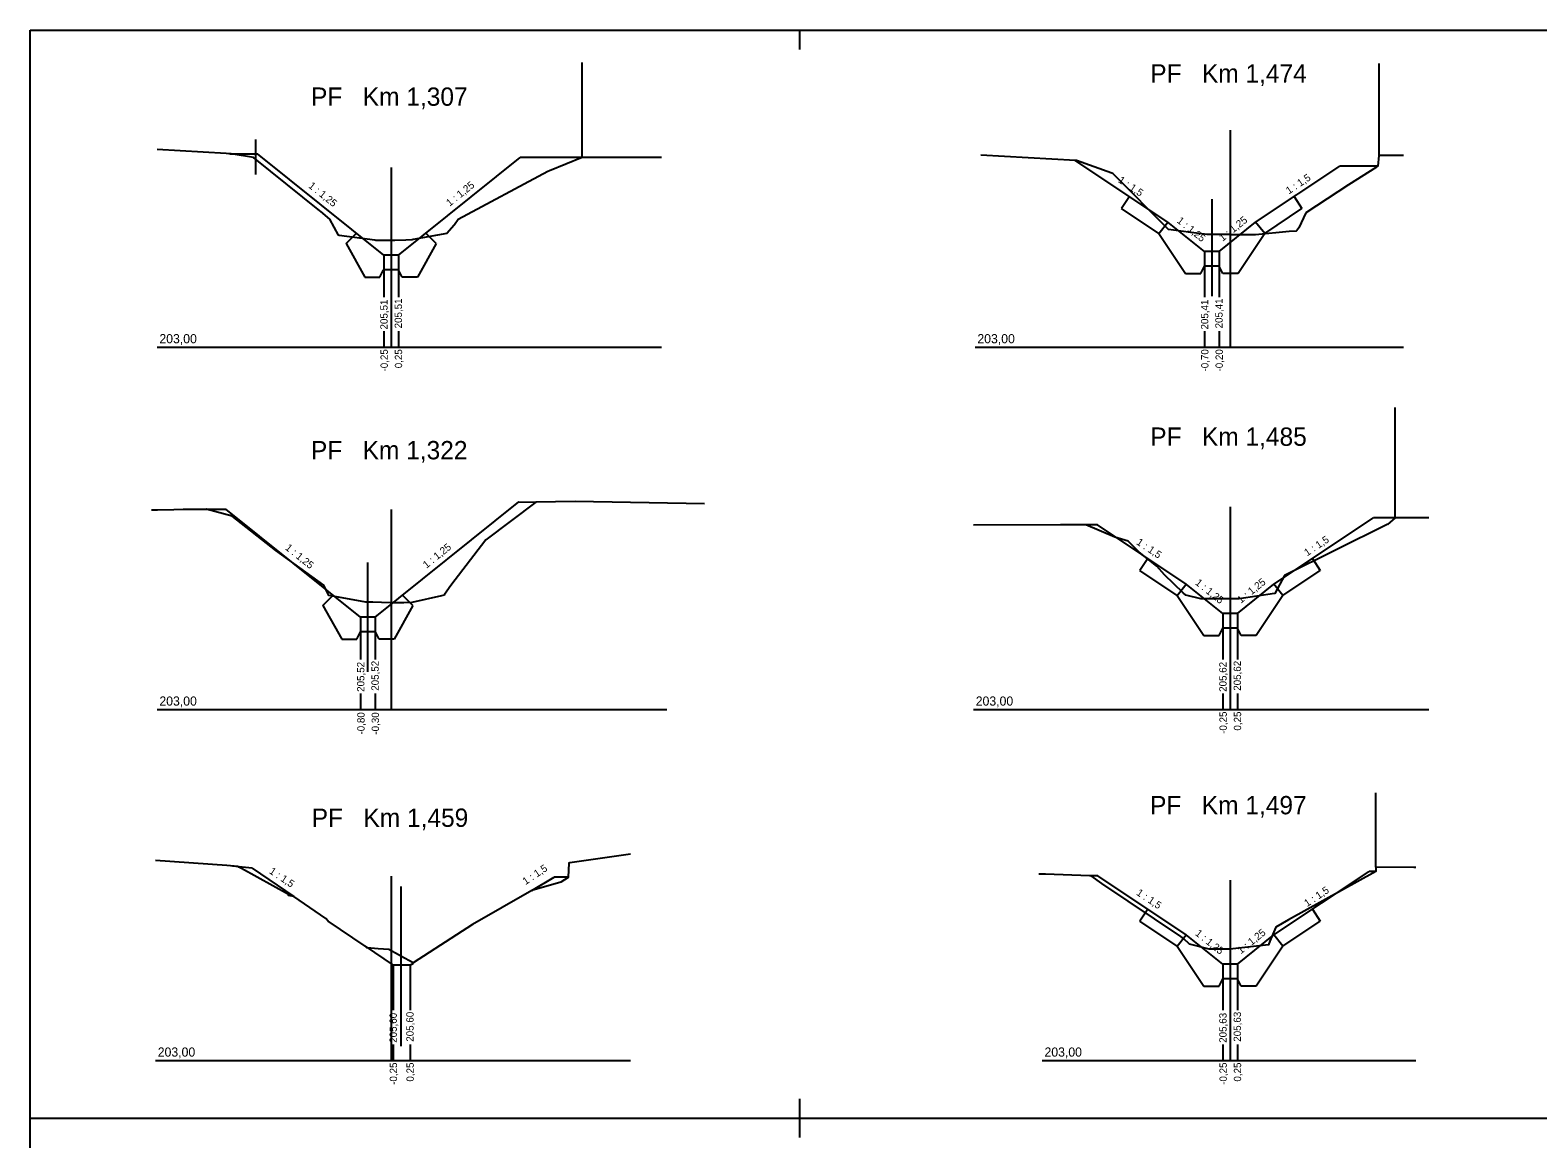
# Model space of a CAD drawing. Extents: x -547174 to -543113, y -1125006 to -1123643.
# Drawn here: x -547152.27 to -547111.11, y -1123808.23 to -1123777.97 of the extents above; entities that cross this region are included whole.
import ezdxf

# ---------------------------------------------------------------- set-up
doc = ezdxf.new("R2010")
doc.units = 0
for name, color, linetype in [('Default', 7, 'Continuous'), ('Profile', 7, 'Continuous'), ('PROFILY NÁVRH', 7, 'Continuous'), ('Section', 7, 'Continuous'), ('STANIČENÍ', 7, 'Continuous')]:
    doc.layers.add(name, color=color, linetype=linetype)

msp = doc.modelspace()

# ---------------------------------------------------------------- linework, layer by layer
at = {"layer": 'Default'}
for points in [[(-547135.036, -1123781.443), (-547137.203, -1123781.442), (-547138.098, -1123781.806), (-547138.143, -1123781.825), (-547140.584, -1123783.136), (-547140.692, -1123783.277), (-547140.699, -1123783.287), (-547140.897, -1123783.518), (-547141.812, -1123783.683), (-547141.841, -1123783.69), (-547142.018, -1123783.695), (-547142.318, -1123783.709), (-547142.34, -1123783.71), (-547142.834, -1123783.71), (-547142.862, -1123783.703), (-547143.838, -1123783.575), (-547143.851, -1123783.559), (-547144.095, -1123783.125), (-547144.334, -1123782.917), (-547144.368, -1123782.894), (-547146.171, -1123781.444), (-547146.781, -1123781.343), (-547146.847, -1123781.34), (-547146.919, -1123781.336), (-547148.807, -1123781.222)], [(-547114.777, -1123781.389), (-547115.442, -1123781.388), (-547115.455, -1123781.389), (-547115.482, -1123781.677), (-547115.484, -1123781.678), (-547115.492, -1123781.682), (-547115.519, -1123781.702), (-547116.277, -1123782.19), (-547117.45, -1123782.95), (-547117.633, -1123783.367), (-547117.689, -1123783.433), (-547117.702, -1123783.445), (-547117.706, -1123783.449), (-547117.899, -1123783.466), (-547118.824, -1123783.553), (-547118.842, -1123783.552), (-547119.489, -1123783.551), (-547119.492, -1123783.549), (-547120.143, -1123783.549), (-547120.144, -1123783.549), (-547120.654, -1123783.482), (-547121.191, -1123783.411), (-547121.194, -1123783.41), (-547121.2, -1123783.404), (-547122.698, -1123781.901), (-547122.718, -1123781.881), (-547122.743, -1123781.874), (-547123.704, -1123781.521), (-547123.737, -1123781.521), (-547126.315, -1123781.375)], [(-547133.864, -1123790.897), (-547137.392, -1123790.831), (-547138.466, -1123790.849), (-547139.83, -1123791.877), (-547140.787, -1123793.125), (-547140.96, -1123793.376), (-547140.974, -1123793.393), (-547141.039, -1123793.405), (-547141.855, -1123793.595), (-547142.069, -1123793.602), (-547142.445, -1123793.601), (-547142.921, -1123793.584), (-547143.104, -1123793.584), (-547144.054, -1123793.405), (-547144.122, -1123793.397), (-547144.122, -1123793.397), (-547144.139, -1123793.366), (-547144.255, -1123793.115), (-547145.569, -1123792.172), (-547146.755, -1123791.236), (-547147.466, -1123791.041), (-547148.797, -1123791.066), (-547148.96, -1123791.066)], [(-547114.086, -1123791.281), (-547114.949, -1123791.279), (-547115.008, -1123791.278), (-547115.22, -1123791.457), (-547115.225, -1123791.464), (-547118.009, -1123792.841), (-547118.025, -1123792.85), (-547118.026, -1123792.853), (-547118.295, -1123793.346), (-547118.301, -1123793.347), (-547119.264, -1123793.491), (-547119.959, -1123793.491), (-547119.96, -1123793.491), (-547119.961, -1123793.491), (-547120.294, -1123793.492), (-547120.31, -1123793.492), (-547120.31, -1123793.492), (-547120.721, -1123793.389), (-547120.795, -1123793.324), (-547121.304, -1123792.831), (-547121.515, -1123792.595), (-547121.997, -1123792.218), (-547122.299, -1123791.916), (-547122.663, -1123791.809), (-547123.448, -1123791.473), (-547124.141, -1123791.473), (-547126.521, -1123791.477)], [(-547135.88, -1123800.459), (-547137.542, -1123800.7), (-547137.57, -1123800.709), (-547137.581, -1123801.085), (-547137.582, -1123801.095), (-547137.782, -1123801.222), (-547138.573, -1123801.454), (-547140.197, -1123802.383), (-547141.815, -1123803.43), (-547142.149, -1123803.248), (-547142.15, -1123803.248), (-547142.151, -1123803.248), (-547142.218, -1123803.21), (-547142.476, -1123803.067), (-547142.477, -1123803.067), (-547142.774, -1123803.043), (-547143.069, -1123803.019), (-547143.081, -1123803.02), (-547143.083, -1123803.021), (-547143.129, -1123802.972), (-547144.134, -1123802.286), (-547144.203, -1123802.22), (-547145.075, -1123801.617), (-547145.216, -1123801.585), (-547145.224, -1123801.565), (-547146.507, -1123800.854), (-547146.571, -1123800.815), (-547146.6, -1123800.802), (-547146.901, -1123800.773), (-547148.852, -1123800.633)], [(-547114.444, -1123800.827), (-547114.498, -1123800.828), (-547115.534, -1123800.816), (-547115.533, -1123800.932), (-547115.537, -1123800.938), (-547117.916, -1123802.253), (-547118.262, -1123802.453), (-547118.425, -1123802.836), (-547118.462, -1123802.933), (-547119.521, -1123803.053), (-547119.523, -1123803.053), (-547119.525, -1123803.053), (-547119.909, -1123803.053), (-547119.91, -1123803.053), (-547120.079, -1123803.053), (-547120.082, -1123803.052), (-547120.618, -1123802.922), (-547120.623, -1123802.918), (-547120.787, -1123802.76), (-547120.857, -1123802.713), (-547123.014, -1123801.259), (-547123.309, -1123801.054), (-547123.353, -1123801.051), (-547124.551, -1123801.004), (-547124.738, -1123801.007)]]:
    msp.add_lwpolyline(points, dxfattribs=at)
at = {"layer": 'Profile'}
for p, q in [((-547152.272, -1123777.966), (-547131.272, -1123777.966)), ((-547152.272, -1123807.666), (-547152.272, -1123777.966)), ((-547131.272, -1123777.966), (-547110.272, -1123777.966)), ((-547131.272, -1123777.966), (-547131.272, -1123778.494)), ((-547131.272, -1123807.138), (-547131.272, -1123807.666)), ((-547152.272, -1123807.666), (-547138.818, -1123807.666)), ((-547152.272, -1123807.666), (-547131.272, -1123807.666)), ((-547152.272, -1123837.366), (-547152.272, -1123807.666)), ((-547131.272, -1123807.666), (-547115.303, -1123807.666)), ((-547131.272, -1123807.666), (-547110.272, -1123807.666)), ((-547131.272, -1123807.666), (-547131.272, -1123808.194))]:
    msp.add_line(p, q, dxfattribs=at)
at = {"layer": 'PROFILY NÁVRH'}
for p, q in [((-547146.118, -1123780.955), (-547146.118, -1123781.906)), ((-547146.814, -1123781.342), (-547146.067, -1123781.342)), ((-547142.618, -1123784.109), (-547146.067, -1123781.342)), ((-547142.218, -1123784.109), (-547138.893, -1123781.442)), ((-547137.203, -1123781.442), (-547138.893, -1123781.442)), ((-547121.21, -1123783.209), (-547123.743, -1123781.52)), ((-547118.816, -1123783.209), (-547116.518, -1123781.677)), ((-547115.48, -1123781.677), (-547116.518, -1123781.677)), ((-547122.258, -1123782.511), (-547122.476, -1123782.837)), ((-547120.013, -1123782.577), (-547120.013, -1123785.225)), ((-547117.768, -1123782.511), (-547117.551, -1123782.837)), ((-547121.457, -1123783.516), (-547122.476, -1123782.837)), ((-547121.457, -1123783.516), (-547121.21, -1123783.209)), ((-547120.213, -1123784.009), (-547121.21, -1123783.209)), ((-547119.813, -1123784.009), (-547118.816, -1123783.209)), ((-547118.57, -1123783.516), (-547118.816, -1123783.209)), ((-547118.57, -1123783.516), (-547117.551, -1123782.837)), ((-547143.648, -1123783.792), (-547143.365, -1123783.509)), ((-547141.187, -1123783.792), (-547141.47, -1123783.509)), ((-547121.457, -1123783.516), (-547120.728, -1123784.609)), ((-547118.57, -1123783.516), (-547119.298, -1123784.609)), ((-547143.648, -1123783.792), (-547143.133, -1123784.709)), ((-547141.187, -1123783.792), (-547141.702, -1123784.709)), ((-547119.813, -1123784.009), (-547120.213, -1123784.009)), ((-547120.213, -1123784.009), (-547120.213, -1123785.251)), ((-547119.813, -1123784.009), (-547119.813, -1123785.251)), ((-547142.218, -1123784.109), (-547142.618, -1123784.109)), ((-547142.618, -1123784.109), (-547142.618, -1123785.251)), ((-547142.218, -1123784.109), (-547142.218, -1123785.251)), ((-547120.313, -1123784.609), (-547120.213, -1123784.409)), ((-547119.813, -1123784.409), (-547120.213, -1123784.409)), ((-547119.713, -1123784.609), (-547119.813, -1123784.409)), ((-547143.133, -1123784.709), (-547142.722, -1123784.709)), ((-547142.722, -1123784.709), (-547142.622, -1123784.509)), ((-547142.214, -1123784.509), (-547142.614, -1123784.509)), ((-547142.114, -1123784.709), (-547142.214, -1123784.509)), ((-547141.702, -1123784.709), (-547142.114, -1123784.709)), ((-547120.728, -1123784.609), (-547120.313, -1123784.609)), ((-547119.298, -1123784.609), (-547119.713, -1123784.609)), ((-547142.618, -1123786.186), (-547142.618, -1123786.619)), ((-547142.218, -1123786.186), (-547142.218, -1123786.619)), ((-547120.213, -1123786.186), (-547120.213, -1123786.619)), ((-547119.813, -1123786.186), (-547119.813, -1123786.619)), ((-547148.099, -1123791.041), (-547146.928, -1123791.041)), ((-547143.251, -1123793.991), (-547146.928, -1123791.041)), ((-547142.851, -1123793.991), (-547138.931, -1123790.846)), ((-547138.931, -1123790.846), (-547138.466, -1123790.849)), ((-547123.138, -1123791.473), (-547123.448, -1123791.473)), ((-547120.71, -1123793.091), (-547123.138, -1123791.473)), ((-547118.316, -1123793.091), (-547115.596, -1123791.278)), ((-547115.008, -1123791.278), (-547115.596, -1123791.278)), ((-547143.051, -1123795.482), (-547143.051, -1123792.498)), ((-547121.758, -1123792.393), (-547121.976, -1123792.719)), ((-547117.268, -1123792.393), (-547117.051, -1123792.719)), ((-547120.957, -1123793.399), (-547121.976, -1123792.719)), ((-547120.957, -1123793.399), (-547120.71, -1123793.091)), ((-547119.713, -1123793.891), (-547120.71, -1123793.091)), ((-547119.313, -1123793.891), (-547118.316, -1123793.091)), ((-547118.07, -1123793.399), (-547118.316, -1123793.091)), ((-547118.07, -1123793.399), (-547117.051, -1123792.719)), ((-547144.282, -1123793.674), (-547143.999, -1123793.391)), ((-547141.821, -1123793.674), (-547142.103, -1123793.391)), ((-547120.957, -1123793.399), (-547120.228, -1123794.491)), ((-547118.07, -1123793.399), (-547118.798, -1123794.491)), ((-547144.282, -1123793.674), (-547143.766, -1123794.591)), ((-547141.821, -1123793.674), (-547142.336, -1123794.591)), ((-547119.313, -1123793.891), (-547119.713, -1123793.891)), ((-547119.713, -1123793.891), (-547119.713, -1123795.143)), ((-547119.313, -1123793.891), (-547119.313, -1123795.143)), ((-547142.851, -1123793.991), (-547143.251, -1123793.991)), ((-547143.251, -1123793.991), (-547143.251, -1123795.143)), ((-547142.851, -1123793.991), (-547142.851, -1123795.143)), ((-547119.813, -1123794.491), (-547119.713, -1123794.291)), ((-547119.313, -1123794.291), (-547119.713, -1123794.291)), ((-547119.213, -1123794.491), (-547119.313, -1123794.291)), ((-547143.766, -1123794.591), (-547143.355, -1123794.591)), ((-547143.355, -1123794.591), (-547143.255, -1123794.391)), ((-547142.847, -1123794.391), (-547143.247, -1123794.391)), ((-547142.747, -1123794.591), (-547142.847, -1123794.391)), ((-547142.336, -1123794.591), (-547142.747, -1123794.591)), ((-547120.228, -1123794.491), (-547119.813, -1123794.491)), ((-547118.798, -1123794.491), (-547119.213, -1123794.491)), ((-547143.251, -1123796.078), (-547143.251, -1123796.511)), ((-547142.851, -1123796.078), (-547142.851, -1123796.511)), ((-547119.713, -1123796.078), (-547119.713, -1123796.511)), ((-547119.313, -1123796.078), (-547119.313, -1123796.511)), ((-547146.214, -1123800.84), (-547146.751, -1123800.787)), ((-547146.214, -1123800.84), (-547145.075, -1123801.617)), ((-547118.316, -1123802.663), (-547115.72, -1123800.932)), ((-547115.533, -1123800.932), (-547115.72, -1123800.932)), ((-547142.145, -1123805.701), (-547142.145, -1123801.344)), ((-547138.573, -1123801.454), (-547137.968, -1123801.085)), ((-547137.581, -1123801.085), (-547137.968, -1123801.085)), ((-547123.123, -1123801.054), (-547123.309, -1123801.054)), ((-547120.71, -1123802.663), (-547123.123, -1123801.054)), ((-547121.758, -1123801.964), (-547121.976, -1123802.29)), ((-547117.268, -1123801.964), (-547117.051, -1123802.29)), ((-547120.957, -1123802.97), (-547121.976, -1123802.29)), ((-547118.07, -1123802.97), (-547117.051, -1123802.29)), ((-547143.129, -1123802.972), (-547142.365, -1123803.493)), ((-547120.957, -1123802.97), (-547120.71, -1123802.663)), ((-547120.957, -1123802.97), (-547120.228, -1123804.063)), ((-547119.713, -1123803.463), (-547120.71, -1123802.663)), ((-547119.313, -1123803.463), (-547118.316, -1123802.663)), ((-547118.07, -1123802.97), (-547118.798, -1123804.063)), ((-547118.07, -1123802.97), (-547118.316, -1123802.663)), ((-547141.9, -1123803.493), (-547142.365, -1123803.493)), ((-547142.365, -1123803.493), (-547142.365, -1123804.724)), ((-547141.9, -1123803.493), (-547141.81, -1123803.433)), ((-547141.9, -1123803.493), (-547141.9, -1123804.724)), ((-547119.313, -1123803.463), (-547119.713, -1123803.463)), ((-547119.713, -1123803.463), (-547119.713, -1123804.724)), ((-547119.313, -1123803.463), (-547119.313, -1123804.724)), ((-547120.228, -1123804.063), (-547119.813, -1123804.063)), ((-547119.813, -1123804.063), (-547119.713, -1123803.863)), ((-547119.313, -1123803.863), (-547119.713, -1123803.863)), ((-547119.213, -1123804.063), (-547119.313, -1123803.863)), ((-547118.798, -1123804.063), (-547119.213, -1123804.063)), ((-547142.365, -1123805.659), (-547142.365, -1123806.093)), ((-547141.9, -1123805.659), (-547141.9, -1123806.093)), ((-547119.713, -1123805.659), (-547119.713, -1123806.093)), ((-547119.313, -1123805.659), (-547119.313, -1123806.093))]:
    msp.add_line(p, q, dxfattribs=at)
at = {"layer": 'Section'}
for p, q in [((-547119.513, -1123780.7), (-547119.513, -1123786.619)), ((-547142.418, -1123781.717), (-547142.418, -1123786.619)), ((-547148.807, -1123786.619), (-547135.036, -1123786.619)), ((-547126.476, -1123786.619), (-547114.777, -1123786.619)), ((-547142.418, -1123791.054), (-547142.418, -1123796.511)), ((-547119.513, -1123790.979), (-547119.513, -1123796.511)), ((-547148.807, -1123796.511), (-547134.892, -1123796.511)), ((-547126.521, -1123796.511), (-547114.086, -1123796.511)), ((-547142.418, -1123801.06), (-547142.418, -1123806.093)), ((-547119.513, -1123801.17), (-547119.513, -1123806.093)), ((-547148.852, -1123806.093), (-547135.88, -1123806.093)), ((-547124.645, -1123806.093), (-547114.444, -1123806.093))]:
    msp.add_line(p, q, dxfattribs=at)
at = {"layer": 'STANIČENÍ'}
for p, q in [((-547137.203, -1123781.442), (-547137.203, -1123778.845)), ((-547115.442, -1123781.388), (-547115.442, -1123778.875)), ((-547115.008, -1123791.278), (-547115.008, -1123788.263)), ((-547115.534, -1123800.816), (-547115.534, -1123798.79))]:
    msp.add_line(p, q, dxfattribs=at)

# ---------------------------------------------------------------- texts
at = {"layer": 'PROFILY NÁVRH'}
for s, rotation, p in [('1 : 1,5', 326.3099, (-547122.589, -1123782.105)), ('1 : 1,5', 33.6901, (-547117.909, -1123782.452)), ('1 : 1,25', 321.2587, (-547144.692, -1123782.246)), ('1 : 1,25', 38.7413, (-547140.818, -1123782.788)), ('1 : 1,25', 321.2587, (-547120.983, -1123783.201)), ('1 : 1,25', 38.7413, (-547119.718, -1123783.743)), ('205,51', 90, (-547142.122, -1123786.108)), ('205,41', 90, (-547119.718, -1123786.108)), ('205,51', 90, (-547142.514, -1123786.138)), ('205,41', 90, (-547120.11, -1123786.138)), ('-0,25', 90, (-547142.508, -1123787.285)), ('0,25', 90, (-547142.117, -1123787.196)), ('-0,70', 90, (-547120.104, -1123787.285)), ('-0,20', 90, (-547119.712, -1123787.285)), ('1 : 1,5', 326.3099, (-547122.089, -1123791.988)), ('1 : 1,5', 33.6901, (-547117.409, -1123792.334)), ('1 : 1,25', 321.2587, (-547145.326, -1123792.128)), ('1 : 1,25', 38.7413, (-547141.452, -1123792.67)), ('1 : 1,25', 321.2587, (-547120.483, -1123793.083)), ('1 : 1,25', 38.7413, (-547119.218, -1123793.625)), ('205,52', 90, (-547143.148, -1123796.03)), ('205,52', 90, (-547142.756, -1123796)), ('205,62', 90, (-547119.61, -1123796.03)), ('205,62', 90, (-547119.218, -1123796)), ('-0,80', 90, (-547143.142, -1123797.195)), ('-0,30', 90, (-547142.75, -1123797.198)), ('-0,25', 90, (-547119.604, -1123797.177)), ('0,25', 90, (-547119.212, -1123797.088)), ('1 : 1,5', 326.3099, (-547145.764, -1123800.97)), ('1 : 1,5', 33.6901, (-547138.748, -1123801.307)), ('1 : 1,5', 33.6901, (-547117.409, -1123801.905)), ('1 : 1,5', 326.3099, (-547122.089, -1123801.559)), ('1 : 1,25', 321.2587, (-547120.483, -1123802.655)), ('1 : 1,25', 38.7413, (-547119.218, -1123803.196)), ('205,60', 90, (-547142.262, -1123805.611)), ('205,60', 90, (-547141.804, -1123805.581)), ('205,63', 90, (-547119.61, -1123805.611)), ('205,63', 90, (-547119.218, -1123805.581)), ('-0,25', 90, (-547142.256, -1123806.758)), ('0,25', 90, (-547141.799, -1123806.67)), ('-0,25', 90, (-547119.604, -1123806.758)), ('0,25', 90, (-547119.212, -1123806.67))]:
    msp.add_text(s, height=0.2, rotation=rotation, dxfattribs=at).set_placement(p)
at = {"layer": 'Section'}
for s, height, p in [('PF   Km 1,474', 0.5, (-547121.694, -1123779.397)), ('PF   Km 1,307', 0.5, (-547144.603, -1123780.031)), ('203,00', 0.25, (-547148.744, -1123786.514)), ('203,00', 0.25, (-547126.413, -1123786.514)), ('PF   Km 1,485', 0.5, (-547121.694, -1123789.313)), ('PF   Km 1,322', 0.5, (-547144.607, -1123789.682)), ('203,00', 0.25, (-547148.744, -1123796.406)), ('203,00', 0.25, (-547126.458, -1123796.406)), ('PF   Km 1,497', 0.5, (-547121.698, -1123799.373)), ('PF   Km 1,459', 0.5, (-547144.585, -1123799.715)), ('203,00', 0.25, (-547148.789, -1123805.988)), ('203,00', 0.25, (-547124.581, -1123805.988))]:
    msp.add_text(s, height=height, dxfattribs=at).set_placement(p)

doc.saveas('drawing.dxf')
